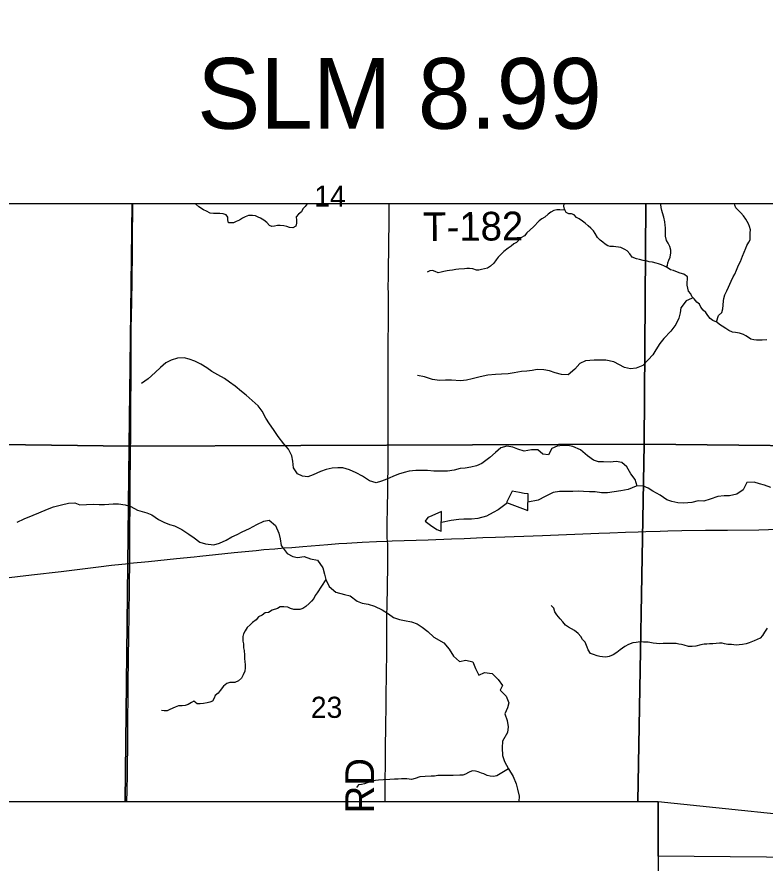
# Model space of a CAD drawing. Extents: x 0 to 34, y 0 to 22.
# Drawn here: x 3.534 to 5.015, y 17.466 to 19.142 of the extents above; entities that cross this region are included whole.
import ezdxf

# ---------------------------------------------------------------- set-up
doc = ezdxf.new("R2010")
doc.units = 0
for name, color, linetype in [('Default', 7, 'Continuous'), ('GM_X_County_Road', 7, 'Continuous'), ('GM_X_County_Road_Text', 7, 'Continuous'), ('GM_X_Minor_Lake', 7, 'Continuous'), ('GM_X_Minor_River', 7, 'Continuous'), ('GM_X_Section', 7, 'Continuous'), ('GM_X_Section_Text', 7, 'Continuous'), ('GM_X_State_Route', 7, 'Continuous'), ('GM_X_Township_Road', 7, 'Continuous'), ('GM_X_Township_Road_Text', 7, 'Continuous'), ('SH_Text', 7, 'Continuous')]:
    doc.layers.add(name, color=color, linetype=linetype)

msp = doc.modelspace()

# ---------------------------------------------------------------- linework, layer by layer
at = {"layer": 'Default'}
msp.add_lwpolyline([(4.804, 17.5881), (5.946, 17.4698), (4.804, 17.4805)], close=True, dxfattribs=at)
at = {"layer": 'GM_X_County_Road'}
for points in [[(4.2678, 18.1041), (4.267, 18.1108), (4.2669, 18.1138), (4.267, 18.1324), (4.2677, 18.1756), (4.2681, 18.1976), (4.2684, 18.2193), (4.2686, 18.2255), (4.2687, 18.2316), (4.2688, 18.2379), (4.2688, 18.2534), (4.2689, 18.2596), (4.2689, 18.2627), (4.2689, 18.2844), (4.2689, 18.303), (4.269, 18.331), (4.2689, 18.35), (4.2689, 18.3711), (4.2688, 18.3931), (4.2691, 18.4335), (4.2693, 18.4801), (4.2693, 18.508), (4.2695, 18.5266), (4.2696, 18.5732), (4.2695, 18.5934), (4.2694, 18.6074), (4.2695, 18.6259), (4.2698, 18.6414), (4.2699, 18.6555), (4.2702, 18.6724), (4.2703, 18.6848), (4.2705, 18.7045), (4.2708, 18.7251), (4.2711, 18.7613), (4.2712, 18.772)], [(4.2632, 17.5881), (4.2633, 17.6108), (4.2634, 17.6325), (4.2637, 17.6605), (4.2639, 17.6915), (4.2643, 17.7412), (4.2649, 17.7754), (4.2649, 17.7972), (4.2662, 17.8841), (4.2664, 17.909), (4.2665, 17.9493), (4.2666, 17.9587), (4.2669, 17.9742), (4.2685, 18.0549), (4.2686, 18.0704), (4.2687, 18.0922), (4.2684, 18.0984), (4.2678, 18.1041)]]:
    msp.add_lwpolyline(points, dxfattribs=at)
at = {"layer": 'GM_X_Minor_Lake'}
for points in [[(4.546, 18.1973), (4.5384, 18.198), (4.529, 18.2002), (4.5145, 18.2028), (4.5037, 18.1807), (4.5454, 18.1646)], [(4.5454, 18.1646), (4.546, 18.1973)], [(4.375, 18.1629), (4.3557, 18.1541), (4.3478, 18.151), (4.3425, 18.1434), (4.3528, 18.1358), (4.3654, 18.1268), (4.3741, 18.1234)], [(4.3741, 18.1234), (4.375, 18.1629)]]:
    msp.add_lwpolyline(points, dxfattribs=at)
at = {"layer": 'GM_X_Minor_River'}
for points in [[(4.1087, 18.772), (4.1049, 18.7666), (4.1003, 18.7617), (4.0977, 18.7559), (4.0917, 18.7514), (4.0871, 18.746), (4.0875, 18.7396), (4.0876, 18.7335), (4.0865, 18.7278), (4.0804, 18.7243), (4.074, 18.7247), (4.0686, 18.7269), (4.0622, 18.7284), (4.0553, 18.7291), (4.05, 18.7287), (4.044, 18.7276), (4.039, 18.7272), (4.0341, 18.729), (4.0287, 18.7351), (4.0227, 18.7396), (4.0166, 18.7434), (4.0116, 18.7457), (4.0063, 18.7479), (4.0002, 18.749), (3.9922, 18.7486), (3.9858, 18.7463), (3.9809, 18.7432), (3.9745, 18.7394), (3.9684, 18.7371), (3.9627, 18.7344), (3.9528, 18.7344), (3.9517, 18.7404), (3.9513, 18.7454), (3.9482, 18.7503), (3.9425, 18.7518), (3.9357, 18.7529), (3.9304, 18.7529), (3.9235, 18.7525), (3.9163, 18.7536), (3.9091, 18.757), (3.9034, 18.76), (3.8939, 18.766), (3.8881, 18.7713), (3.8877, 18.772)], [(4.938, 18.5248), (4.9304, 18.5297), (4.9251, 18.5331), (4.9201, 18.5377), (4.9117, 18.541), (4.9068, 18.5448), (4.9022, 18.5505), (4.898, 18.5566), (4.8927, 18.5615), (4.8885, 18.5672), (4.8858, 18.5729), (4.8804, 18.5774), (4.8747, 18.5835), (4.8705, 18.5884), (4.8682, 18.5933), (4.8636, 18.5986), (4.8624, 18.6051), (4.8613, 18.6108), (4.8613, 18.6165), (4.8616, 18.6218), (4.8616, 18.6271), (4.8543, 18.6324), (4.8471, 18.6347), (4.8422, 18.6362), (4.8338, 18.6399), (4.8281, 18.6414), (4.8216, 18.6456), (4.8163, 18.6486), (4.8106, 18.6508), (4.8045, 18.6527), (4.7996, 18.6542), (4.7924, 18.6561), (4.7859, 18.6568), (4.7798, 18.6591), (4.7741, 18.6594), (4.7665, 18.6613), (4.7608, 18.6628), (4.7525, 18.6662), (4.7475, 18.6726), (4.7425, 18.6787), (4.7376, 18.6817), (4.73, 18.6851), (4.7151, 18.6873), (4.7087, 18.6876), (4.7038, 18.6884), (4.6988, 18.6922), (4.6939, 18.6956), (4.6889, 18.7001), (4.6836, 18.7054), (4.679, 18.713), (4.6759, 18.7183), (4.6702, 18.7236), (4.6652, 18.7281), (4.6591, 18.7338), (4.6538, 18.7372), (4.6473, 18.7421), (4.642, 18.7447), (4.6374, 18.7497), (4.6321, 18.7519), (4.6271, 18.7519), (4.6218, 18.7549), (4.618, 18.761), (4.6172, 18.7674), (4.6176, 18.772)], [(4.8204, 18.6462), (4.822, 18.6494), (4.8227, 18.6551), (4.825, 18.6604), (4.8272, 18.6661), (4.8291, 18.6749), (4.829, 18.6798), (4.8271, 18.6874), (4.8233, 18.6939), (4.8202, 18.6992), (4.8183, 18.7075), (4.8182, 18.7243), (4.8178, 18.7296), (4.817, 18.736), (4.8147, 18.7452), (4.812, 18.7539), (4.8108, 18.7588), (4.8096, 18.7645), (4.8088, 18.7702), (4.8086, 18.772)], [(4.9193, 18.538), (4.9231, 18.5506), (4.9295, 18.5567), (4.9317, 18.564), (4.9325, 18.5712), (4.9332, 18.5795), (4.9335, 18.5845), (4.9358, 18.5917), (4.9399, 18.5997), (4.9433, 18.607), (4.9459, 18.6127), (4.9485, 18.6188), (4.9523, 18.6272), (4.9553, 18.6325), (4.9587, 18.6405), (4.9617, 18.647), (4.9639, 18.6527), (4.9665, 18.6576), (4.9688, 18.6626), (4.9707, 18.6683), (4.9774, 18.6843), (4.9793, 18.6896), (4.983, 18.6957), (4.986, 18.7007), (4.986, 18.7144), (4.9863, 18.7205), (4.9844, 18.7269), (4.9828, 18.7319), (4.9802, 18.7368), (4.9771, 18.7417), (4.9729, 18.7482), (4.9676, 18.7538), (4.9622, 18.7591), (4.9573, 18.7637), (4.9553, 18.7694), (4.9549, 18.772)], [(4.6189, 18.7596), (4.6188, 18.7595), (4.6089, 18.7602), (4.6028, 18.7602), (4.5971, 18.7586), (4.5911, 18.7552), (4.5862, 18.7513), (4.5794, 18.7456), (4.5733, 18.7418), (4.5684, 18.7383), (4.5567, 18.7265), (4.5438, 18.7143), (4.5389, 18.7085), (4.5318, 18.7047), (4.5231, 18.6952), (4.5178, 18.6925), (4.5125, 18.6883), (4.5064, 18.6841), (4.4981, 18.6776), (4.4921, 18.6714), (4.4868, 18.6665), (4.4827, 18.6608), (4.4785, 18.6546), (4.4717, 18.6485), (4.4657, 18.6447), (4.4596, 18.6428), (4.4539, 18.6416), (4.4486, 18.6404), (4.4437, 18.6404), (4.4368, 18.6431), (4.43, 18.6438), (4.4251, 18.6438), (4.4201, 18.6434), (4.4087, 18.6425), (4.4034, 18.6418), (4.3966, 18.6406), (4.3905, 18.6398), (4.3856, 18.6394), (4.3792, 18.6378), (4.3739, 18.6367), (4.3682, 18.6355), (4.3621, 18.6378), (4.3568, 18.6396), (4.3515, 18.6392), (4.3462, 18.6362)], [(4.873, 18.5855), (4.87, 18.5842), (4.859, 18.5799), (4.8485, 18.5662), (4.847, 18.5563), (4.8448, 18.5457), (4.8384, 18.5331), (4.8287, 18.5194), (4.8147, 18.5049), (4.8068, 18.4954), (4.7993, 18.4828), (4.7933, 18.4729), (4.7839, 18.4627), (4.7737, 18.4516), (4.7601, 18.4466), (4.7492, 18.4454), (4.737, 18.448), (4.7158, 18.4592), (4.7002, 18.4625), (4.6904, 18.4625), (4.6771, 18.462), (4.6601, 18.4608), (4.6484, 18.4558), (4.6386, 18.4447), (4.6258, 18.4329), (4.6121, 18.434), (4.5996, 18.4373), (4.5886, 18.441), (4.5776, 18.4432), (4.5643, 18.4435), (4.5541, 18.4416), (4.5435, 18.4404), (4.5333, 18.4396), (4.5189, 18.4372), (4.5068, 18.4352), (4.4936, 18.4344), (4.4815, 18.434), (4.4667, 18.4327), (4.4512, 18.4292), (4.4357, 18.425), (4.4243, 18.4226), (4.4122, 18.4214), (4.3944, 18.4224), (4.3827, 18.4228), (4.3709, 18.4223), (4.3569, 18.4241), (4.341, 18.429), (4.3273, 18.4319)], [(5.0186, 18.5028), (5.0099, 18.502), (4.9985, 18.5019), (4.9932, 18.5023), (4.9875, 18.5041), (4.9825, 18.5072), (4.9776, 18.5106), (4.9726, 18.5132), (4.965, 18.5158), (4.9567, 18.5169), (4.951, 18.518), (4.9437, 18.5207), (4.938, 18.5248)], [(4.7624, 18.213), (4.7579, 18.2262), (4.7499, 18.2375), (4.7419, 18.2511), (4.732, 18.2594), (4.7203, 18.2613), (4.7089, 18.2604), (4.6953, 18.2607), (4.6854, 18.2611), (4.6755, 18.2644), (4.6638, 18.2727), (4.6501, 18.2847), (4.6345, 18.2915), (4.625, 18.2933), (4.614, 18.2936), (4.6038, 18.2917), (4.5932, 18.2871), (4.5869, 18.2749), (4.5755, 18.2763), (4.5656, 18.2846), (4.5531, 18.2846), (4.5387, 18.2818), (4.5258, 18.2859), (4.516, 18.29), (4.5038, 18.2918), (4.4925, 18.2884), (4.4815, 18.2796), (4.4702, 18.2693), (4.4544, 18.2578), (4.4438, 18.2528), (4.4325, 18.2501), (4.4215, 18.2485), (4.4117, 18.2477), (4.3996, 18.2446), (4.3863, 18.2426), (4.3734, 18.2422), (4.3594, 18.2428), (4.3469, 18.2439), (4.3242, 18.2438), (4.3106, 18.2425), (4.3007, 18.2398), (4.2894, 18.2364), (4.2784, 18.2317), (4.2667, 18.2267), (4.2561, 18.2229), (4.2455, 18.2194), (4.2323, 18.2235), (4.2182, 18.2325), (4.206, 18.2393), (4.1924, 18.2453), (4.1795, 18.249), (4.1696, 18.2493), (4.1583, 18.2485), (4.1466, 18.2461), (4.1348, 18.2415), (4.1209, 18.2354), (4.1099, 18.2315), (4.0993, 18.2326), (4.0894, 18.2371), (4.0814, 18.2488), (4.0806, 18.2621), (4.0786, 18.2727), (4.0717, 18.2863), (4.0626, 18.2965), (4.0511, 18.3108), (4.042, 18.3248), (4.0339, 18.3361), (4.0267, 18.3475), (4.0194, 18.3611), (4.0118, 18.3717), (4, 18.3826), (3.9882, 18.3928), (3.9787, 18.4003), (3.9661, 18.4105), (3.9551, 18.4187), (3.9448, 18.4259), (3.9315, 18.4334), (3.9201, 18.4401), (3.9102, 18.4473), (3.8981, 18.4544), (3.8863, 18.4601), (3.8753, 18.4645), (3.8654, 18.4668), (3.8518, 18.4659), (3.8397, 18.4621), (3.8288, 18.4571), (3.8182, 18.4479), (3.8077, 18.4376), (3.7941, 18.425), (3.7809, 18.4162)], [(5.0269, 18.2099), (5.0144, 18.2148), (5.0046, 18.2174), (4.9936, 18.2204), (4.9795, 18.2199), (4.972, 18.2058), (4.9596, 18.1967), (4.9452, 18.1935), (4.9342, 18.1935), (4.9217, 18.1923), (4.907, 18.1869), (4.8941, 18.1834), (4.8832, 18.1837), (4.8707, 18.1806), (4.8548, 18.179), (4.8427, 18.18), (4.8305, 18.1822), (4.821, 18.186), (4.8074, 18.195), (4.7933, 18.2029), (4.7838, 18.2085), (4.7732, 18.2134), (4.7599, 18.2129), (4.7444, 18.206), (4.73, 18.2033), (4.7168, 18.2013), (4.7032, 18.1993), (4.6914, 18.1996), (4.6789, 18.2015), (4.6676, 18.2014), (4.6562, 18.2021), (4.6456, 18.2028), (4.6346, 18.2023), (4.6085, 18.2022), (4.596, 18.2002), (4.5801, 18.1925), (4.5658, 18.1852), (4.5457, 18.1809)], [(3.5347, 18.1417), (3.5483, 18.1478), (3.5661, 18.1555), (3.5774, 18.1597), (3.5944, 18.167), (3.6061, 18.1717), (3.6224, 18.1759), (3.6364, 18.1794), (3.6485, 18.1795), (3.6587, 18.1761), (3.672, 18.1766), (3.6849, 18.1771), (3.697, 18.1767), (3.7076, 18.1768), (3.7246, 18.1777), (3.7352, 18.1777), (3.7481, 18.1755), (3.7595, 18.1722), (3.7724, 18.1654), (3.7914, 18.1602), (3.8013, 18.1557), (3.8142, 18.1471), (3.8248, 18.1415), (3.8362, 18.137), (3.8457, 18.1344), (3.8605, 18.1273), (3.8742, 18.1179), (3.8852, 18.1103), (3.8959, 18.1021), (3.9072, 18.0983), (3.9239, 18.0969), (3.9353, 18.1), (3.9481, 18.1058), (3.9598, 18.1123), (3.97, 18.1173), (3.9798, 18.1223), (3.9946, 18.1288), (4.0093, 18.1372), (4.0229, 18.1438), (4.0335, 18.1453), (4.0457, 18.1352), (4.0529, 18.12), (4.0553, 18.1087), (4.0569, 18.0954), (4.0694, 18.0796), (4.0801, 18.0732), (4.0896, 18.0717), (4.1028, 18.0733), (4.115, 18.0692), (4.129, 18.0662), (4.1397, 18.0508), (4.1428, 18.0386), (4.1455, 18.0277), (4.152, 18.014), (4.1657, 18.0027), (4.1828, 17.9983), (4.1938, 17.9957), (4.2074, 17.9852), (4.2173, 17.9814), (4.2298, 17.9792), (4.2423, 17.9755), (4.2572, 17.968), (4.2697, 17.9601), (4.2796, 17.9526), (4.2914, 17.9485), (4.3016, 17.9466), (4.3156, 17.9444), (4.3262, 17.94), (4.3365, 17.9336), (4.3479, 17.9249), (4.3597, 17.9136), (4.3795, 17.9023), (4.3901, 17.8903), (4.3982, 17.8759), (4.4104, 17.8657), (4.4232, 17.8685), (4.4365, 17.8651), (4.4419, 17.8515), (4.4488, 17.8383), (4.4601, 17.844), (4.4752, 17.8418), (4.4871, 17.8298), (4.4955, 17.8184), (4.491, 17.8086), (4.5028, 17.7972), (4.5081, 17.7836), (4.5052, 17.7737), (4.5003, 17.7623), (4.5049, 17.7487), (4.5065, 17.7362), (4.5051, 17.7252), (4.4953, 17.7081), (4.495, 17.6944), (4.4955, 17.6796), (4.4997, 17.6679), (4.5073, 17.6528), (4.5169, 17.638), (4.5227, 17.6233), (4.5254, 17.613), (4.5285, 17.599), (4.5277, 17.5881)], [(4.5057, 18.1799), (4.4871, 18.1662), (4.4769, 18.1608), (4.4637, 18.1532), (4.4467, 18.1489), (4.4342, 18.1473), (4.419, 18.1472), (4.4092, 18.1468), (4.3937, 18.1448), (4.3745, 18.1411)], [(4.1455, 18.0277), (4.1282, 18.0014), (4.1245, 17.996), (4.1218, 17.9903), (4.1173, 17.9853), (4.1124, 17.9804), (4.106, 17.9743), (4.0999, 17.9708), (4.0942, 17.9689), (4.0882, 17.9685), (4.0825, 17.9688), (4.0756, 17.9707), (4.0703, 17.973), (4.0623, 17.9737), (4.0555, 17.9736), (4.0498, 17.9706), (4.0392, 17.9675), (4.0324, 17.9629), (4.0256, 17.9617), (4.0195, 17.9575), (4.0124, 17.9541), (4.0078, 17.9483), (4.0003, 17.943), (3.9961, 17.938), (3.9901, 17.9327), (3.9859, 17.9266), (3.9829, 17.9205), (3.9814, 17.9151), (3.9815, 17.9056), (3.9823, 17.9003), (3.9827, 17.8927), (3.9842, 17.8874), (3.9847, 17.8779), (3.9847, 17.871), (3.9851, 17.8657), (3.9859, 17.8589), (3.9856, 17.8532), (3.9852, 17.8467), (3.9818, 17.8395), (3.9785, 17.8326), (3.9724, 17.8273), (3.9656, 17.8242), (3.9557, 17.8241), (3.9497, 17.8222), (3.9429, 17.8169), (3.9365, 17.8085), (3.9323, 17.8031), (3.9266, 17.7982), (3.9248, 17.7932), (3.921, 17.7871), (3.9161, 17.7848), (3.9104, 17.784), (3.9036, 17.7825), (3.8971, 17.7821), (3.8911, 17.7816), (3.8846, 17.7869), (3.8797, 17.7846), (3.8732, 17.7804), (3.8668, 17.7785), (3.8611, 17.7781), (3.8539, 17.7777), (3.8474, 17.7754), (3.8368, 17.7708), (3.8312, 17.7681), (3.8255, 17.768), (3.8205, 17.7684)], [(4.9303, 17.9016), (4.9253, 17.9016), (4.9189, 17.9012), (4.9117, 17.9008), (4.9052, 17.9004), (4.9003, 17.9), (4.8946, 17.8999), (4.8885, 17.8984), (4.8783, 17.8961), (4.8711, 17.8956), (4.8639, 17.8956), (4.8555, 17.8978), (4.8498, 17.8993), (4.8449, 17.8997), (4.8392, 17.9012), (4.832, 17.9015), (4.8233, 17.9015), (4.8138, 17.9011), (4.8069, 17.9007), (4.8005, 17.901), (4.7936, 17.9021), (4.7842, 17.9036), (4.7747, 17.9039), (4.7678, 17.9043), (4.7599, 17.9035), (4.7534, 17.9023), (4.7451, 17.8992), (4.7379, 17.895), (4.7288, 17.8885), (4.722, 17.8832), (4.7145, 17.8786), (4.7065, 17.8755), (4.7001, 17.8739), (4.6936, 17.8747), (4.6883, 17.8754), (4.683, 17.8769), (4.6757, 17.8792), (4.6697, 17.8814), (4.6651, 17.8886), (4.6631, 17.8939), (4.6589, 17.9038), (4.654, 17.9095), (4.6509, 17.9148), (4.6455, 17.9208), (4.6383, 17.9273), (4.6318, 17.9303), (4.6265, 17.9337), (4.62, 17.9378), (4.6151, 17.9439), (4.6097, 17.9503), (4.6032, 17.9579), (4.5994, 17.964), (4.5971, 17.9712), (4.5917, 17.9765)], [(5.0193, 17.9317), (5.0144, 17.9237), (5.0103, 17.9168), (5.0054, 17.9118), (5.0001, 17.9092), (4.9936, 17.9068), (4.9838, 17.9026), (4.9777, 17.9003), (4.9709, 17.8991), (4.9641, 17.8987), (4.958, 17.8979), (4.9489, 17.899), (4.942, 17.8994), (4.9352, 17.9009), (4.9303, 17.9016)], [(4.5073, 17.6528), (4.4842, 17.6395), (4.4774, 17.6376), (4.4713, 17.6383), (4.4652, 17.6402), (4.4588, 17.6432), (4.4538, 17.6443), (4.4474, 17.6469), (4.442, 17.6484), (4.4356, 17.6492), (4.4284, 17.6461), (4.4223, 17.6423), (4.417, 17.6407), (4.4113, 17.6403), (4.3981, 17.6399), (4.3905, 17.6398), (4.3855, 17.6398), (4.3791, 17.6402), (4.3738, 17.6401), (4.3673, 17.6397), (4.3609, 17.6389), (4.3544, 17.6385), (4.3423, 17.6381), (4.3317, 17.6373), (4.3226, 17.6342), (4.315, 17.6319), (4.3063, 17.6334), (4.2952, 17.6333), (4.2892, 17.6329), (4.2816, 17.6325), (4.2721, 17.6317), (4.26, 17.6316), (4.2497, 17.6308), (4.2437, 17.6297), (4.2387, 17.6285), (4.233, 17.6273), (4.2277, 17.6254), (4.2221, 17.6235), (4.2164, 17.6219), (4.2103, 17.6215), (4.2065, 17.6162)]]:
    msp.add_lwpolyline(points, dxfattribs=at)
at = {"layer": 'GM_X_Section'}
for points in [[(3.1951, 19.3083), (2.736, 19.3101), (2.7303, 18.305), (3.7563, 18.2917), (3.7624, 18.772), (3.1951, 18.772)], [(4.7796, 18.772), (4.7762, 18.2959), (5.7756, 18.2855), (5.7801, 19.2683), (5.7798, 19.3134), (5.415, 19.3104), (5.415, 18.772)], [(3.7624, 18.772), (3.7563, 18.2917), (4.7762, 18.2959), (4.7796, 18.772)], [(3.7484, 17.5881), (3.7563, 18.2917), (2.7303, 18.305), (2.7229, 17.5881)], [(4.7636, 17.5881), (4.7762, 18.2959), (3.7563, 18.2917), (3.7484, 17.5881)], [(4.804, 17.2765), (5.7727, 17.3042), (5.7758, 18.2578), (5.7756, 18.2855), (4.7762, 18.2959), (4.7636, 17.5881), (4.804, 17.5881)]]:
    msp.add_lwpolyline(points, close=True, dxfattribs=at)
at = {"layer": 'GM_X_State_Route'}
for points in [[(3.8852, 18.0729), (3.8962, 18.0741), (3.9271, 18.0774), (3.9642, 18.0813), (4.0075, 18.0857), (4.0229, 18.0872), (4.0445, 18.089), (4.0631, 18.0905), (4.0786, 18.0915), (4.1003, 18.0932), (4.1498, 18.0976), (4.1715, 18.0993), (4.187, 18.1002), (4.2179, 18.1019), (4.2459, 18.1033), (4.2678, 18.1041), (4.2769, 18.1044), (4.3482, 18.1068), (4.3948, 18.1086), (4.4196, 18.1094), (4.4568, 18.111), (4.4815, 18.1118), (4.5746, 18.1153), (4.6864, 18.1195), (4.7081, 18.1202), (4.7391, 18.1215), (4.7639, 18.1223), (4.7794, 18.1228), (4.8074, 18.1239), (4.8229, 18.1244), (4.8508, 18.125), (4.8974, 18.1254), (4.9409, 18.1256), (5.003, 18.1265), (5.0993, 18.1293)], [(3.7565, 18.0599), (3.7574, 18.06), (3.7943, 18.0637), (3.8499, 18.0694), (3.8852, 18.0729)], [(3.5076, 18.0305), (3.5631, 18.0373), (3.6216, 18.0439), (3.6585, 18.0484), (3.6954, 18.0531), (3.7213, 18.0561), (3.7417, 18.0584), (3.7565, 18.0599)]]:
    msp.add_lwpolyline(points, dxfattribs=at)
at = {"layer": 'GM_X_Township_Road'}
for points in [[(3.7574, 18.06), (3.7574, 18.0606), (3.7574, 18.0916), (3.7577, 18.132), (3.7581, 18.1724), (3.7582, 18.1879), (3.7581, 18.2127), (3.7582, 18.228), (3.7588, 18.2615), (3.7594, 18.3287), (3.7597, 18.3816), (3.7599, 18.4189), (3.7602, 18.4561), (3.7602, 18.4934), (3.7605, 18.5245), (3.7615, 18.5773), (3.762, 18.6208), (3.7623, 18.6363), (3.7626, 18.6611), (3.7629, 18.6984), (3.7637, 18.772)], [(3.7519, 17.5881), (3.7521, 17.6105), (3.7526, 17.6416), (3.7526, 17.6571), (3.7529, 17.6724), (3.7533, 17.6847), (3.7536, 17.7033), (3.7537, 17.75), (3.7542, 17.7966), (3.7545, 17.8276), (3.7546, 17.8649), (3.7554, 17.9239), (3.7559, 17.9488), (3.7568, 18.0202), (3.7574, 18.06)]]:
    msp.add_lwpolyline(points, dxfattribs=at)
at = {"layer": 'SH_Text'}
for points in [[(3.1951, 19.4891), (5.415, 19.4891), (5.415, 18.772), (3.1951, 18.772)], [(2.5841, 17.5881), (4.804, 17.5881), (4.804, 16.8709), (2.5841, 16.8709)]]:
    msp.add_lwpolyline(points, close=True, dxfattribs=at)

# ---------------------------------------------------------------- texts
at = {"layer": 'GM_X_County_Road_Text'}
msp.add_text('RD', height=0.05682, rotation=90, dxfattribs=at).set_placement((4.2411, 17.5648))
at = {"layer": 'GM_X_Section_Text'}
for s, p in [('14', (4.1227, 18.766)), ('23', (4.116, 17.754))]:
    msp.add_text(s, height=0.04186, rotation=0, dxfattribs=at).set_placement(p)
at = {"layer": 'GM_X_Township_Road_Text'}
msp.add_text('T-182', height=0.05682, rotation=0.5624, dxfattribs=at).set_placement((4.3384, 18.6978))
at = {"layer": 'SH_Text'}
msp.add_text('SLM 8.99', height=0.14, dxfattribs=at).set_placement((3.8909, 18.9205))

doc.saveas('drawing.dxf')
